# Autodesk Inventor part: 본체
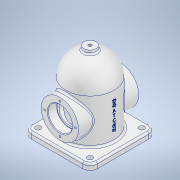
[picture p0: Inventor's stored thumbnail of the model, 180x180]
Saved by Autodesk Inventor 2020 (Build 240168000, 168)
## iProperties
Created: 2021-07
Part Number: 본체
Material: 알루미늄 6061
Document SubType Name: Modeling
Designer: Owner
Mass: 865.906 g
Surface Area: 800.746 cm^2
Volume: 320.706 cm^3
Density: 2.7 g/cm^3
Appearance: 알루미늄 - 평지
Author: Owner
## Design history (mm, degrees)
sketch "스케치1"
  geometry: C1 r 40 at (0, 0); 1 further point
  constraints: 1 centre point, 1 coincident
  dimensions: "d0" = 80 diameter of C1
extrude "돌출1" new body sketch "스케치1" distance "d1" = 124; taper "d2" = 0 deg
fillet "모깎기1" dims "d3" = 40
feature "쉘1" dims "d4" = 8
node "작업 평면2"
sketch "스케치2"
  geometry: L1 (40, 84)-(-40, 84) reference; C1 r 31 at (0, 48); 1 further point
  constraints: 1 centre point, 1 vertical alignment
  dimensions: "d7" = 62 diameter of C1; "d8" = 48 distance of point (0, 0) C1.centre
extrude "돌출2" join sketch "스케치2" stored distance "d9" = 129; taper "d10" = 0 deg
sketch "스케치3"
  geometry: C1 r 31 at (0, 0) reference; 2 further points
  constraints: 1 coincident
hole "구멍1" sketch "스케치3" at (0, 0) diameter "d11" = 40; stored, may be unused: countersink angle "d15" = 90 deg, drill point angle "d17" = 0 deg; dims "d12" = 50, "d13" = 4, "d14" = 2, "d16" = 15
sketch "스케치4"
  geometry: C1 r 20 at (0, 0) reference; 2 further points
  constraints: 1 coincident
hole "구멍2" sketch "스케치4" at (0, 0) diameter "d18" = 33; stored, may be unused: countersink angle "d22" = 90 deg, drill point angle "d24" = 0 deg; dims "d19" = 50, "d20" = 4, "d21" = 2, "d23" = 15
sketch "스케치5"
  geometry: C1 r 31 at (0, 0) reference; 2 further points
  constraints: 1 vertical alignment
  dimensions: "d25" = 25.5 distance of C1.centre point (0, 25.5)
hole "구멍3" sketch "스케치5" at (0, 25.5) diameter "d26" = 3.242; stored, may be unused: countersink angle "d30" = 90 deg, drill point angle "d32" = 118 deg; dims "d27" = 8, "d28" = 4, "d29" = 2, "d31" = 10
node "작업 평면3"
sketch "스케치6"
  geometry: C1 r 10 at (0, 0); 1 further point
  constraints: 1 centre point, 1 coincident
  dimensions: "d37" = 20 diameter of C1
extrude "돌출3" join sketch "스케치6" stored distance "d38" = 124; taper "d39" = 0 deg
sketch "스케치7"
  geometry: C1 r 10 at (0, 0) reference; 2 further points
  constraints: 1 coincident
hole "구멍4" sketch "스케치7" at (0, 0) diameter "d40" = 5.1881; stored, may be unused: countersink angle "d44" = 90 deg, drill point angle "d46" = 118 deg; dims "d41" = 12, "d42" = 4, "d43" = 2, "d45" = 16
sketch "스케치8"
  geometry: L1 (-55, 55)-(55, 55); L2 (55, 55)-(55, -55); L3 (55, -55)-(-55, -55); L4 (-55, -55)-(-55, 55); C1 r 32 at (0, 0) reference; 3 further points
  constraints: 8 end point, 2 midpoint, 2 parallel, 1 horizontal, 1 horizontal alignment, 1 perpendicular, 1 vertical alignment
  dimensions: "d47" = 110 distance of L1.start L1.end; "d48" = 110 distance of L1.end L2.end
extrude "돌출4" join sketch "스케치8" distance "d49" = 10; taper "d50" = 0 deg
fillet "모깎기2" dims "d51" = 12
sketch "스케치9"
  geometry: A1 r 12 centre (-43, -43) between (-55, -43) and (-43, -55) reference; 2 further points
  constraints: 1 coincident
hole "구멍5" sketch "스케치9" at (-43, -43) diameter "d52" = 9; stored, may be unused: countersink angle "d56" = 90 deg, drill point angle "d58" = 0 deg; dims "d53" = 12, "d54" = 4, "d55" = 2, "d57" = 16
node "작업 평면4"
sketch "스케치10"
  geometry: L1 (0, -43)-(0, 43) reference; 3 further points
  constraints: 1 horizontal alignment, 1 midpoint, 1 other
  dimensions: "d62" = 48 distance from line of L1 point (48, 0)
feature "엠보싱1" sketch "스케치10" dims "d1" = 124, "d2" = 0, "d63" = 0.5, "d64" = 0
fillet "모깎기3" dims "d65" = 3
fillet "모깎기4" dims "d66" = 3
fillet "모깎기5" dims "d67" = 3
fillet "모깎기6" dims "d68" = 0.3
chamfer "모따기1" distance "d69" = 1; stored, may be unused: second distance "d70" = 2, angle "d71" = 45 deg
node "솔리드1"
pattern_circular "원형 패턴1" dims angle "d34" = 360 deg
mirror "미러1"
pattern_circular "원형 패턴2" dims angle "d60" = 360 deg
node "투영된 루프1"
feature "A9D066F2-1C7D-4E18-AEED-F7BC21143FA4" dims "d11" = 40, "d12" = 50, "d13" = 4, "d14" = 2, "d15" = 90 deg, "d16" = 15, "d17" = 0
other parameters: "d36" = 129
